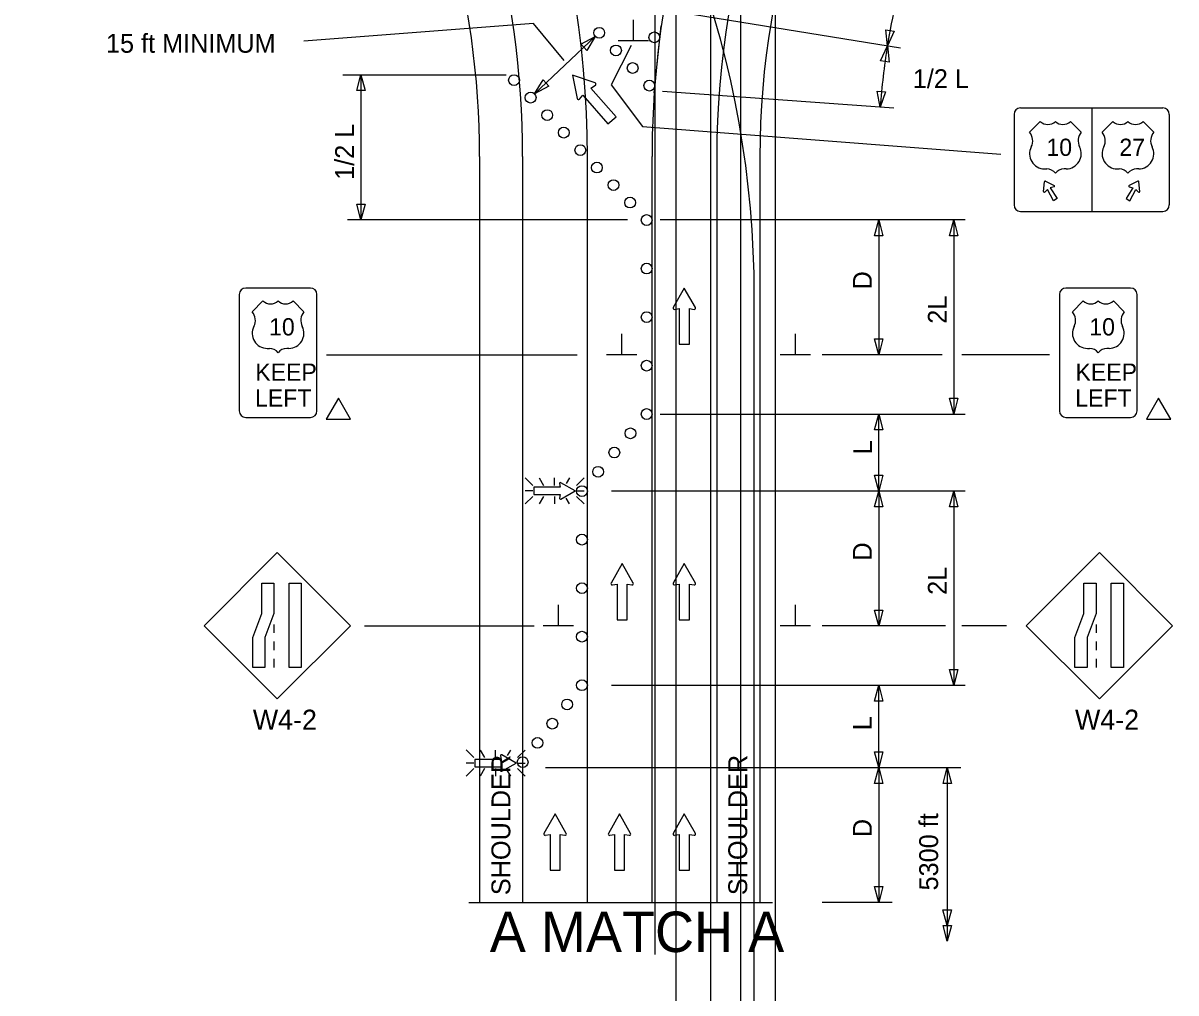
# Model space of a CAD drawing. Extents: x 16728 to 19508, y 5553 to 7079.
# Drawn here: x 16738.5 to 17166.2, y 6124.8 to 6484.5 of the extents above; entities that cross this region are included whole.
import ezdxf

# ---------------------------------------------------------------- set-up
doc = ezdxf.new("R2010")
doc.units = 0
for name, color, linetype in [('ALI_LEGAL_EX', 7, 'Continuous'), ('MT_SCRATCH_LEVEL_E', 7, 'Continuous'), ('PAVT_EDGE_EX', 7, 'Continuous'), ('TRAFFIC_SIGNS_PR', 7, 'Continuous'), ('TYPICAL_EX', 7, 'Continuous'), ('TYPICAL_TEXT_DIMEN_PR', 7, 'Continuous')]:
    doc.layers.add(name, color=color, linetype=linetype)

msp = doc.modelspace()

# ---------------------------------------------------------------- linework, layer by layer
at = {"layer": 'ALI_LEGAL_EX'}
for p, q in [((16980.68, 6974.12), (16980.68, 6155.98)), ((17004.68, 6974.12), (17004.68, 6155.98)), ((16980.68, 6877.04), (16980.68, 6013.12)), ((17004.68, 6877.04), (17004.68, 6013.12)), ((16973.01, 6139.03), (16973.01, 6639.38)), ((16993.65, 6024.8), (16993.65, 6525.15)), ((17017.65, 6024.8), (17017.65, 6525.15)), ((16947.82, 6158.38), (16947.82, 6435.06)), ((16971.82, 6158.38), (16971.82, 6435.06)), ((17009.75, 5773.57), (17009.75, 6383.76))]:
    msp.add_line(p, q, dxfattribs=at)
for points in [[(16972.59, 6458.6), (16975.21, 6483.46)], [(16947.82, 6358.38), (16947.82, 6383.38)], [(16971.82, 6358.38), (16971.82, 6383.38)], [(16947.82, 6258.38), (16947.82, 6283.38)], [(16971.82, 6258.38), (16971.82, 6283.38)], [(16947.82, 6158.38), (16947.82, 6183.38)], [(16971.82, 6158.38), (16971.82, 6183.38)]]:
    msp.add_lwpolyline(points, dxfattribs=at)
for centre, radius, start, end in [((16583.82, 6435.06), 364, 0, 40.1909), ((17311.82, 6435.06), 340, 137.516, 180), ((16645.75, 6383.76), 364, 0, 40.1909)]:
    msp.add_arc(centre, radius, start, end, dxfattribs=at)
at = {"layer": 'MT_SCRATCH_LEVEL_E'}
for p, q in [((16983.79, 6386.25), (16979.68, 6379.01)), ((16987.94, 6379.01), (16983.79, 6386.25)), ((16980.16, 6378.32), (16981.94, 6378.64)), ((16981.94, 6378.64), (16981.94, 6365.38)), ((16985.68, 6365.38), (16985.68, 6378.64)), ((16985.68, 6378.64), (16987.46, 6378.32)), ((16981.94, 6365.38), (16985.68, 6365.38)), ((16960.72, 6284.09), (16956.61, 6276.85)), ((16964.86, 6276.85), (16960.72, 6284.09)), ((16983.79, 6284.09), (16979.68, 6276.85)), ((16987.94, 6276.85), (16983.79, 6284.09)), ((16957.09, 6276.17), (16958.87, 6276.48)), ((16958.87, 6276.48), (16958.87, 6263.23)), ((16962.61, 6263.23), (16962.61, 6276.48)), ((16962.61, 6276.48), (16964.39, 6276.17)), ((16980.16, 6276.17), (16981.94, 6276.48)), ((16981.94, 6276.48), (16981.94, 6263.23)), ((16985.68, 6263.23), (16985.68, 6276.48)), ((16985.68, 6276.48), (16987.46, 6276.17)), ((16958.87, 6263.23), (16962.61, 6263.23)), ((16981.94, 6263.23), (16985.68, 6263.23)), ((16935.83, 6191.19), (16931.72, 6183.95)), ((16939.98, 6183.95), (16935.83, 6191.19)), ((16959.74, 6191.19), (16955.62, 6183.95)), ((16963.88, 6183.95), (16959.74, 6191.19)), ((16983.79, 6191.19), (16979.68, 6183.95)), ((16987.94, 6183.95), (16983.79, 6191.19)), ((16932.2, 6183.27), (16933.98, 6183.58)), ((16933.98, 6183.58), (16933.98, 6170.32)), ((16937.72, 6170.32), (16937.72, 6183.58)), ((16937.72, 6183.58), (16939.5, 6183.27)), ((16956.11, 6183.27), (16957.88, 6183.58)), ((16957.88, 6183.58), (16957.88, 6170.32)), ((16961.63, 6170.32), (16961.63, 6183.58)), ((16961.63, 6183.58), (16963.4, 6183.27)), ((16980.16, 6183.27), (16981.94, 6183.58)), ((16981.94, 6183.58), (16981.94, 6170.32)), ((16985.68, 6170.32), (16985.68, 6183.58)), ((16985.68, 6183.58), (16987.46, 6183.27)), ((16933.98, 6170.32), (16937.72, 6170.32)), ((16957.88, 6170.32), (16961.63, 6170.32)), ((16981.94, 6170.32), (16985.68, 6170.32))]:
    msp.add_line(p, q, dxfattribs=at)
for centre, start, end in [((16980.09, 6378.78), 150.4248, 279.9638), ((16987.53, 6378.78), 260.0362, 29.7731), ((16957.01, 6276.63), 150.4248, 279.9638), ((16964.46, 6276.63), 260.0362, 29.7731), ((16980.09, 6276.63), 150.4248, 279.9638), ((16987.53, 6276.63), 260.0362, 29.7731), ((16932.13, 6183.72), 150.4248, 279.9638), ((16939.57, 6183.73), 260.0362, 29.7731), ((16956.03, 6183.72), 150.4248, 279.9638), ((16963.47, 6183.73), 260.0362, 29.7731), ((16980.09, 6183.72), 150.4248, 279.9638), ((16987.53, 6183.73), 260.0362, 29.7731)]:
    msp.add_arc(centre, 0.463, start, end, dxfattribs=at)
at = {"layer": 'PAVT_EDGE_EX'}
for p, q in [((16907.82, 6435.06), (16907.82, 6158.38)), ((16923.82, 6435.06), (16923.82, 6158.38)), ((16995.82, 6435.06), (16995.82, 6158.38)), ((17011.82, 6435.06), (17011.82, 6158.38))]:
    msp.add_line(p, q, dxfattribs=at)
for centre, radius, start, end in [((17311.82, 6435.06), 316, 105.2177, 180), ((16583.82, 6435.06), 340, 0, 61.4862), ((17311.82, 6435.06), 300, 105.2177, 180), ((16583.82, 6435.06), 324, 0, 61.4862), ((17311.82, 6435.06), 300, 180, 180.00000277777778)]:
    msp.add_arc(centre, radius, start, end, dxfattribs=at)
at = {"layer": 'TRAFFIC_SIGNS_PR'}
for p, q in [((17106.11, 6450.65), (17106.11, 6417.05)), ((17108.51, 6453.05), (17161.31, 6453.05)), ((17134.91, 6453.05), (17134.91, 6414.65)), ((17163.71, 6450.65), (17163.71, 6417.05)), ((17117.09, 6422), (17117.37, 6425.62)), ((17117.74, 6425.84), (17121.02, 6424.27)), ((17152.07, 6425.84), (17148.8, 6424.27)), ((17152.73, 6422), (17152.44, 6425.62)), ((17108.51, 6414.65), (17161.31, 6414.65)), ((16845.09, 6386.26), (16821.09, 6386.26)), ((17149.37, 6386.26), (17125.37, 6386.26)), ((16818.69, 6383.86), (16818.69, 6340.66)), ((16847.49, 6340.66), (16847.49, 6383.86)), ((17122.97, 6383.86), (17122.97, 6340.66)), ((17151.77, 6340.66), (17151.77, 6383.86)), ((16821.09, 6338.26), (16845.09, 6338.26)), ((17125.37, 6338.26), (17149.37, 6338.26)), ((16927.59, 6313.05), (16924.77, 6315.87)), ((16929.89, 6315.87), (16931.52, 6313.05)), ((16935.68, 6313.05), (16935.68, 6315.87)), ((16941.15, 6315.87), (16939.94, 6313.77)), ((16946.58, 6315.86), (16943.76, 6313.05)), ((16927.59, 6311.02), (16924.77, 6311.02)), ((16927.59, 6308.98), (16924.77, 6306.16)), ((16931.54, 6308.98), (16929.91, 6306.16)), ((16935.68, 6308.98), (16935.68, 6306.16)), ((16943.76, 6311.02), (16946.58, 6311.02)), ((16946.58, 6306.16), (16943.76, 6308.98)), ((16939.86, 6308.35), (16941.12, 6306.16)), ((16832.78, 6288.17), (16805.62, 6261.02)), ((16859.93, 6261.02), (16832.78, 6288.17)), ((17137.78, 6288.17), (17110.62, 6261.02)), ((17164.93, 6261.02), (17137.78, 6288.17)), ((16831.53, 6261.51), (16831.53, 6258.31)), ((17136.53, 6261.51), (17136.53, 6258.31)), ((16805.62, 6261.02), (16832.78, 6233.86)), ((16832.78, 6233.86), (16859.93, 6261.02)), ((17110.62, 6261.02), (17137.78, 6233.86)), ((17137.78, 6233.86), (17164.93, 6261.02)), ((16831.53, 6255.11), (16831.53, 6251.91)), ((17136.53, 6255.11), (17136.53, 6251.91)), ((16831.53, 6248.71), (16831.53, 6245.51)), ((17136.53, 6248.71), (17136.53, 6245.51)), ((16905.72, 6212.1), (16902.9, 6214.92)), ((16908.01, 6214.91), (16909.64, 6212.1)), ((16913.8, 6212.1), (16913.8, 6214.91)), ((16919.27, 6214.91), (16918.06, 6212.82)), ((16924.71, 6214.91), (16921.89, 6212.1)), ((16905.72, 6210.06), (16902.9, 6210.06)), ((16921.89, 6210.06), (16924.71, 6210.06)), ((16905.72, 6208.03), (16902.9, 6205.21)), ((16909.67, 6208.03), (16908.04, 6205.21)), ((16913.8, 6208.03), (16913.8, 6205.21)), ((16917.99, 6207.4), (16919.25, 6205.21)), ((16924.71, 6205.21), (16921.89, 6208.03))]:
    msp.add_line(p, q, dxfattribs=at)
for points in [[(17120.98, 6423.79), (17119.57, 6423.4), (17122.08, 6419.42), (17120.76, 6418.65), (17118.57, 6422.82), (17117.53, 6421.79)], [(17148.83, 6423.79), (17150.24, 6423.4), (17147.73, 6419.42), (17149.06, 6418.65), (17151.25, 6422.82), (17152.29, 6421.79)], [(16937.5, 6313.7), (16937.73, 6312.4), (16928.01, 6312.4), (16928.01, 6309.66), (16937.73, 6309.66), (16937.5, 6308.35)], [(16938, 6308), (16943.31, 6311.02), (16938, 6314.06)], [(16915.63, 6212.74), (16915.86, 6211.45), (16906.14, 6211.45), (16906.14, 6208.7), (16915.86, 6208.7), (16915.63, 6207.4)], [(16916.13, 6207.05), (16921.44, 6210.06), (16916.13, 6213.1)]]:
    msp.add_lwpolyline(points, dxfattribs=at)
for points in [[(16831.53, 6276.75), (16831.53, 6265.57), (16828.19, 6256.69), (16828.19, 6245.51), (16823.69, 6245.51), (16823.69, 6256.69), (16827.04, 6265.57), (16827.04, 6276.75)], [(16841.67, 6276.75), (16841.67, 6245.51), (16837.17, 6245.51), (16837.17, 6276.75)], [(17136.53, 6276.75), (17136.53, 6265.57), (17133.18, 6256.69), (17133.18, 6245.51), (17128.69, 6245.51), (17128.69, 6256.69), (17132.03, 6265.57), (17132.03, 6276.75)], [(17146.66, 6276.75), (17146.66, 6245.51), (17142.17, 6245.51), (17142.17, 6276.75)]]:
    msp.add_lwpolyline(points, close=True, dxfattribs=at)
for centre in [(16952.24, 6480.91), (16972.68, 6479.22), (16958.43, 6474.38), (16964.62, 6467.85), (16920.63, 6463.35), (16970.82, 6461.32), (16926.78, 6456.87), (16932.93, 6450.38), (16939.07, 6443.89), (16945.22, 6437.4), (16951.37, 6430.92), (16957.52, 6424.43), (16963.67, 6417.94), (16969.82, 6411.46), (16969.82, 6411.46), (16969.82, 6393.46), (16969.82, 6375.46), (16969.82, 6357.46), (16969.82, 6339.51), (16963.82, 6332.37), (16957.82, 6325.23), (16951.82, 6318.09), (16945.82, 6310.95), (16945.82, 6292.94), (16945.82, 6274.94), (16945.82, 6256.94), (16945.82, 6238.94), (16940.32, 6231.81), (16934.82, 6224.69), (16929.32, 6217.56), (16923.83, 6210.43)]:
    msp.add_circle(centre, 2, dxfattribs=at)
for centre, radius, start, end in [((17108.51, 6450.65), 2.4, 90, 180), ((17108.51, 6450.65), 2.4, 90, 180), ((17161.31, 6450.65), 2.4, 0, 90), ((17117.63, 6425.6), 0.26, 64.4823, 175.5177), ((17120.91, 6424.04), 0.26, 285.9885, 64.4823), ((17148.91, 6424.04), 0.26, 115.5177, 254.0115), ((17152.19, 6425.6), 0.26, 4.4823, 115.5177), ((17117.35, 6421.98), 0.26, 175.5177, 314.0115), ((17152.47, 6421.98), 0.26, 225.9885, 4.4823), ((17108.51, 6417.05), 2.4, 180, 270), ((17161.31, 6417.05), 2.4, 270, 0), ((16821.09, 6383.86), 2.4, 90, 180), ((16845.09, 6383.86), 2.4, 0, 90), ((17125.37, 6383.86), 2.4, 90, 180), ((17149.37, 6383.86), 2.4, 0, 90), ((16821.09, 6340.66), 2.4, 180, 270), ((16845.09, 6340.66), 2.4, 270, 0), ((17125.37, 6340.66), 2.4, 180, 270), ((17149.37, 6340.66), 2.4, 270, 0), ((16937.84, 6313.76), 0.341, 61.4833, 189.9593), ((16937.84, 6308.3), 0.341, 170.7308, 298.8916), ((16915.97, 6212.8), 0.341, 61.4833, 189.9593), ((16915.97, 6207.35), 0.341, 170.7308, 298.8916)]:
    msp.add_arc(centre, radius, start, end, dxfattribs=at)
at = {"layer": 'TYPICAL_EX'}
for p, q in [((17111.86, 6444.05), (17115.86, 6448.05)), ((17131.06, 6444.05), (17127.06, 6448.05)), ((17138.76, 6444.05), (17142.76, 6448.05)), ((17157.96, 6444.05), (17153.96, 6448.05)), ((17117.45, 6430.44), (17118.25, 6430.44)), ((17125.46, 6430.44), (17124.66, 6430.44)), ((17144.35, 6430.44), (17145.15, 6430.44)), ((17152.36, 6430.44), (17151.56, 6430.44)), ((16823.49, 6377.46), (16827.49, 6381.46)), ((16842.69, 6377.46), (16838.69, 6381.46)), ((17127.77, 6377.46), (17131.77, 6381.46)), ((17146.97, 6377.46), (17142.97, 6381.46)), ((16829.09, 6363.85), (16829.89, 6363.85)), ((16837.1, 6363.85), (16836.3, 6363.85)), ((17133.36, 6363.85), (17134.16, 6363.85)), ((17141.37, 6363.85), (17140.57, 6363.85))]:
    msp.add_line(p, q, dxfattribs=at)
for centre, radius, start, end in [((17118.66, 6450.96), 4.04, 226.1404, 313.8596), ((17124.26, 6450.96), 4.04, 226.1404, 313.8596), ((17145.56, 6450.96), 4.04, 226.1404, 313.8596), ((17151.16, 6450.96), 4.04, 226.1404, 313.8596), ((17108.07, 6440.85), 4.96, 333.0977, 40.1936), ((17134.85, 6440.85), 4.96, 139.8064, 206.9023), ((17134.97, 6440.85), 4.96, 333.0977, 40.1936), ((17161.75, 6440.85), 4.96, 139.8064, 206.9023), ((17117.46, 6436.03), 5.59, 152.6698, 269.9013), ((17125.45, 6436.03), 5.59, 270.0987, 27.3302), ((17144.36, 6436.03), 5.59, 152.6698, 269.9013), ((17152.35, 6436.03), 5.59, 270.0987, 27.3302), ((17118.26, 6426.43), 4.01, 37.1038, 90.1385), ((17124.65, 6426.43), 4.01, 89.8615, 142.8962), ((17145.16, 6426.43), 4.01, 37.1038, 90.1385), ((17151.55, 6426.43), 4.01, 89.8615, 142.8962), ((16830.29, 6384.37), 4.04, 226.1404, 313.8596), ((16835.89, 6384.37), 4.04, 226.1404, 313.8596), ((17134.57, 6384.37), 4.04, 226.1404, 313.8596), ((17140.17, 6384.37), 4.04, 226.1404, 313.8596), ((16819.7, 6374.26), 4.96, 333.0977, 40.1936), ((16846.49, 6374.26), 4.96, 139.8064, 206.9023), ((17123.98, 6374.26), 4.96, 333.0977, 40.1936), ((17150.76, 6374.26), 4.96, 139.8064, 206.9023), ((16829.1, 6369.44), 5.59, 152.6698, 269.9013), ((16837.09, 6369.44), 5.59, 270.0987, 27.3302), ((17133.37, 6369.44), 5.59, 152.6698, 269.9013), ((17141.36, 6369.44), 5.59, 270.0987, 27.3302), ((16829.9, 6359.84), 4.01, 37.1038, 90.1385), ((16836.29, 6359.84), 4.01, 89.8615, 142.8962), ((17134.17, 6359.84), 4.01, 37.1038, 90.1385), ((17140.56, 6359.84), 4.01, 89.8615, 142.8962)]:
    msp.add_arc(centre, radius, start, end, dxfattribs=at)
at = {"layer": 'TYPICAL_TEXT_DIMEN_PR'}
for p, q in [((17064.05, 6475.22), (16979.21, 6488.97)), ((16927.8, 6484.32), (16842.59, 6477.76)), ((16939.16, 6470.62), (16927.8, 6484.32)), ((16964.92, 6477.95), (16964.92, 6485.73)), ((16950.78, 6479.54), (16928.23, 6458.24)), ((16945.44, 6476.66), (16950.78, 6479.54)), ((16950.78, 6479.54), (16947.6, 6474.37)), ((17059.11, 6476.02), (17058.5, 6482.06)), ((17058.5, 6482.06), (17060.05, 6481.81)), ((17059.11, 6476.02), (17058.5, 6482.06)), ((17058.5, 6482.06), (17060.05, 6481.81)), ((17061.6, 6481.55), (17059.11, 6476.02)), ((17061.6, 6481.55), (17059.11, 6476.02)), ((17060.05, 6481.81), (17061.6, 6481.55)), ((17060.05, 6481.81), (17061.6, 6481.55)), ((16946.52, 6475.52), (16945.44, 6476.66)), ((16947.6, 6474.37), (16946.52, 6475.52)), ((16964.04, 6476.17), (16956.66, 6461.67)), ((16970.55, 6477.95), (16959.3, 6477.95)), ((17056.63, 6470.48), (17059.11, 6476.02)), ((17059.11, 6476.02), (17059.73, 6469.98)), ((17058.18, 6470.23), (17056.63, 6470.48)), ((17059.73, 6469.98), (17058.18, 6470.23)), ((16857.14, 6465.35), (16917.72, 6465.35)), ((16862.25, 6459.49), (16863.82, 6465.35)), ((16863.82, 6465.35), (16863.82, 6411.51)), ((16863.82, 6465.35), (16865.39, 6459.49)), ((16928.23, 6458.24), (16931.41, 6463.41)), ((16931.41, 6463.41), (16932.49, 6462.26)), ((16950.7, 6462.31), (16942.28, 6465.2)), ((16942.28, 6465.2), (16944.08, 6456.51)), ((16863.82, 6459.49), (16862.25, 6459.49)), ((16865.39, 6459.49), (16863.82, 6459.49)), ((16933.57, 6461.12), (16928.23, 6458.24)), ((16932.49, 6462.26), (16933.57, 6461.12)), ((16949.15, 6460.43), (16950.8, 6461.43)), ((16958.47, 6449.8), (16949.15, 6460.43)), ((16956.66, 6461.67), (16968.23, 6446.16)), ((17061.46, 6452.97), (16975.72, 6459.1)), ((17056.47, 6453.32), (17055.32, 6459.28)), ((17055.32, 6459.28), (17056.89, 6459.17)), ((17058.45, 6459.06), (17056.47, 6453.32)), ((17056.89, 6459.17), (17058.45, 6459.06)), ((16944.95, 6456.3), (16946.15, 6457.8)), ((16946.15, 6457.8), (16955.47, 6447.16)), ((16955.47, 6447.16), (16958.47, 6449.8)), ((16968.23, 6446.16), (17101.17, 6435.93)), ((16863.82, 6411.51), (16862.25, 6417.37)), ((16862.25, 6417.37), (16863.82, 6417.37)), ((16863.82, 6417.37), (16865.39, 6417.37)), ((16865.39, 6417.37), (16863.82, 6411.51)), ((16962.71, 6411.51), (16858.82, 6411.51)), ((17087.96, 6411.51), (16974.86, 6411.51)), ((17054.34, 6405.65), (17055.91, 6411.51)), ((17055.91, 6411.51), (17057.48, 6405.65)), ((17055.91, 6411.51), (17055.91, 6361.51)), ((17082.15, 6405.65), (17083.72, 6411.51)), ((17083.72, 6411.51), (17083.72, 6339.51)), ((17083.72, 6411.51), (17085.29, 6405.65)), ((17055.91, 6405.65), (17054.34, 6405.65)), ((17057.48, 6405.65), (17055.91, 6405.65)), ((17083.72, 6405.65), (17082.15, 6405.65)), ((17085.29, 6405.65), (17083.72, 6405.65)), ((16960.57, 6361.51), (16960.57, 6369.29)), ((17025.04, 6361.51), (17025.04, 6369.29)), ((17055.91, 6361.51), (17054.34, 6367.37)), ((17054.34, 6367.37), (17055.91, 6367.37)), ((17055.91, 6367.37), (17057.48, 6367.37)), ((17057.48, 6367.37), (17055.91, 6361.51)), ((16851.1, 6361.51), (16944.03, 6361.51)), ((16966.19, 6361.51), (16954.94, 6361.51)), ((17030.66, 6361.51), (17019.41, 6361.51)), ((17079.49, 6361.51), (17034.91, 6361.51)), ((17119.26, 6361.51), (17086.72, 6361.51)), ((17083.72, 6339.51), (17082.15, 6345.37)), ((17082.15, 6345.37), (17083.72, 6345.37)), ((17083.72, 6345.37), (17085.29, 6345.37)), ((17085.29, 6345.37), (17083.72, 6339.51)), ((16974.86, 6339.51), (17087.96, 6339.51)), ((17054.34, 6333.65), (17055.91, 6339.51)), ((17055.91, 6310.94), (17055.91, 6339.51)), ((17055.91, 6339.51), (17057.48, 6333.65)), ((17055.91, 6333.65), (17054.34, 6333.65)), ((17057.48, 6333.65), (17055.91, 6333.65)), ((17055.91, 6310.94), (17054.34, 6316.81)), ((17054.34, 6316.81), (17055.91, 6316.81)), ((17055.91, 6316.81), (17057.48, 6316.81)), ((17057.48, 6316.81), (17055.91, 6310.94)), ((17087.96, 6310.94), (16956.81, 6310.94)), ((17054.34, 6305.08), (17055.91, 6310.94)), ((17055.91, 6310.94), (17055.91, 6260.94)), ((17055.91, 6310.94), (17057.48, 6305.08)), ((17082.15, 6305.08), (17083.72, 6310.94)), ((17083.72, 6310.94), (17085.29, 6305.08)), ((17083.72, 6310.94), (17083.72, 6238.94)), ((17055.91, 6305.08), (17054.34, 6305.08)), ((17057.48, 6305.08), (17055.91, 6305.08)), ((17083.72, 6305.08), (17082.15, 6305.08)), ((17085.29, 6305.08), (17083.72, 6305.08)), ((16937.1, 6260.94), (16937.1, 6268.73)), ((17025.04, 6260.94), (17025.04, 6268.73)), ((17055.91, 6260.94), (17054.34, 6266.81)), ((17054.34, 6266.81), (17055.91, 6266.81)), ((17055.91, 6266.81), (17057.48, 6266.81)), ((17057.48, 6266.81), (17055.91, 6260.94)), ((16865.1, 6260.94), (16928.11, 6260.94)), ((16942.73, 6260.94), (16931.48, 6260.94)), ((17030.66, 6260.94), (17019.41, 6260.94)), ((17080.65, 6260.94), (17034.91, 6260.94)), ((17103.35, 6260.94), (17086.72, 6260.94)), ((17083.72, 6238.94), (17082.15, 6244.81)), ((17082.15, 6244.81), (17083.72, 6244.81)), ((17083.72, 6244.81), (17085.29, 6244.81)), ((17085.29, 6244.81), (17083.72, 6238.94)), ((16956.81, 6238.94), (17087.96, 6238.94)), ((17054.34, 6233.08), (17055.91, 6238.94)), ((17055.91, 6208.38), (17055.91, 6238.94)), ((17055.91, 6238.94), (17057.48, 6233.08)), ((17055.91, 6233.08), (17054.34, 6233.08)), ((17057.48, 6233.08), (17055.91, 6233.08)), ((17055.91, 6208.38), (17054.34, 6214.24)), ((17054.34, 6214.24), (17055.91, 6214.24)), ((17055.91, 6214.24), (17057.48, 6214.24)), ((17057.48, 6214.24), (17055.91, 6208.38)), ((16932.31, 6208.38), (17086.35, 6208.38)), ((16933.08, 6208.38), (17060.91, 6208.38)), ((17054.34, 6202.52), (17055.91, 6208.38)), ((17055.91, 6208.38), (17055.91, 6158.38)), ((17055.91, 6208.38), (17057.48, 6202.52)), ((17079.78, 6202.52), (17081.35, 6208.38)), ((17081.35, 6208.38), (17081.35, 6143.96)), ((17081.35, 6208.38), (17082.92, 6202.52)), ((17055.91, 6202.52), (17054.34, 6202.52)), ((17057.48, 6202.52), (17055.91, 6202.52)), ((17081.35, 6202.52), (17079.78, 6202.52)), ((17082.92, 6202.52), (17081.35, 6202.52)), ((17055.91, 6158.38), (17054.34, 6164.24)), ((17054.34, 6164.24), (17055.91, 6164.24)), ((17055.91, 6164.24), (17057.48, 6164.24)), ((17057.48, 6164.24), (17055.91, 6158.38)), ((16903.89, 6158.38), (17016.54, 6158.38)), ((17060.91, 6158.38), (17034.91, 6158.38)), ((17081.32, 6149.82), (17079.75, 6155.68)), ((17079.75, 6155.68), (17081.32, 6155.68)), ((17081.32, 6155.68), (17082.89, 6155.68)), ((17082.89, 6155.68), (17081.32, 6149.82)), ((17081.35, 6143.96), (17079.78, 6149.83)), ((17079.78, 6149.83), (17081.35, 6149.83)), ((17081.35, 6149.83), (17082.92, 6149.83)), ((17082.92, 6149.83), (17081.35, 6143.96))]:
    msp.add_line(p, q, dxfattribs=at)
for points in [[(16855.46, 6345.44), (16850.93, 6337.6), (16859.98, 6337.6)], [(17159.74, 6345.44), (17155.21, 6337.6), (17164.26, 6337.6)]]:
    msp.add_lwpolyline(points, close=True, dxfattribs=at)
for centre, radius, start, end in [((17311.82, 6435.06), 256, 167.0592, 170.7929), ((17311.82, 6435.06), 256, 170.7929, 175.9084), ((16950.53, 6461.84), 0.494, 301.2737, 71.0106), ((16944.56, 6456.61), 0.494, 191.6624, 321.2013)]:
    msp.add_arc(centre, radius, start, end, dxfattribs=at)

# ---------------------------------------------------------------- texts
at = {"layer": 'TRAFFIC_SIGNS_PR'}
for s, height, p in [('10', 6.4, (17118.12, 6435.25)), ('27', 6.4, (17145.19, 6435.25)), ('10', 6.4, (16829.75, 6368.66)), ('10', 6.4, (17134.03, 6368.66)), ('KEEP', 6.4, (16824.63, 6351.86)), ('KEEP', 6.4, (17128.9, 6351.86)), ('LEFT', 6.4, (16824.54, 6342.26)), ('LEFT', 6.4, (17128.82, 6342.26)), ('W4-2', 7.44, (16823.73, 6222.43)), ('W4-2', 7.44, (17128.73, 6222.43))]:
    msp.add_text(s, height=height, dxfattribs=at).set_placement(p)
at = {"layer": 'TYPICAL_TEXT_DIMEN_PR'}
for s, height, p in [('15 ft MINIMUM', 7, (16769.25, 6473.51)), ('1/2 L', 7, (17068.56, 6460.4)), ('A MATCH A', 15, (16911.63, 6139.98))]:
    msp.add_text(s, height=height, dxfattribs=at).set_placement(p)
for s, p in [('1/2 L', (16861.26, 6426.37)), ('D', (17053.35, 6385.73)), ('2L', (17081.16, 6373.01)), ('L', (17053.45, 6324.58)), ('D', (17053.35, 6285.16)), ('2L', (17081.16, 6272.45)), ('L', (17053.35, 6222.24)), ('SHOULDER', (16919.25, 6161.09)), ('SHOULDER', (17007.11, 6161.09)), ('D', (17053.35, 6182.6)), ('5300 ft', (17077.94, 6162.83))]:
    msp.add_text(s, height=7, rotation=90, dxfattribs=at).set_placement(p)

doc.saveas('drawing.dxf')
